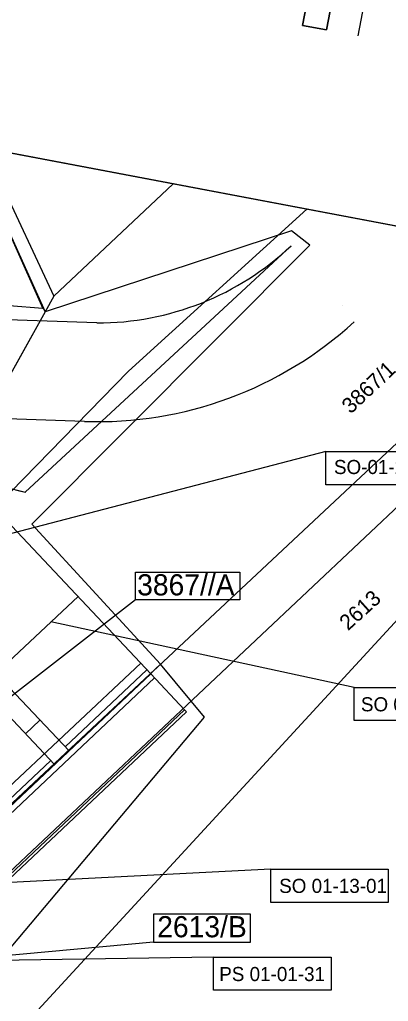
# Model space of a CAD drawing. Extents: x -526979 to -525529, y -1078878 to -1076692.
# Drawn here: x -526680.9 to -526628.5, y -1078144.8 to -1078005.6 of the extents above; entities that cross this region are included whole.
import ezdxf

# ---------------------------------------------------------------- set-up
doc = ezdxf.new("R2010")
doc.units = 0
for name, color, linetype in [('DZ_DO_ostatní', 7, 'Continuous'), ('Hranice parcel', 7, 'Continuous'), ('legenda barvy', 7, 'Continuous'), ('Parcelní čísla', 7, 'Continuous'), ('SO 01-50-01 silnice', 7, 'Continuous'), ('SO 01-50-01 silnice odvodnění', 7, 'Continuous'), ('Vnitřní kresba', 7, 'Continuous'), ('Vrstva 10', 7, 'Continuous'), ('Vrstva 12', 7, 'Continuous'), ('Vrstva 21', 7, 'Continuous'), ('Vrstva 63', 7, 'Continuous')]:
    doc.layers.add(name, color=color, linetype=linetype)

msp = doc.modelspace()

# ---------------------------------------------------------------- linework, layer by layer
at = {"layer": 'DZ_DO_ostatní'}
for points in [[(-526703.48, -1078093.97), (-526704.77, -1078090.39), (-526703.79, -1078090.05), (-526704.64, -1078087.24), (-526706.6, -1078087.88), (-526707.36, -1078085.92), (-526725.33, -1078039.65), (-526687.74, -1078023.95), (-526677.32, -1078047.05)], [(-526660.92, -1078096.98), (-526679.17, -1078077.14), (-526639.73, -1078037.59), (-526642.32, -1078035.55), (-526677.32, -1078047.05), (-526703.48, -1078093.97), (-526693.98, -1078127.86)], [(-526691.28, -1078138.22), (-526690.31, -1078138), (-526688.44, -1078144.53), (-526654.67, -1078104.54), (-526660.92, -1078096.98), (-526693.98, -1078127.86)]]:
    msp.add_lwpolyline(points, close=True, dxfattribs=at)
at = {"layer": 'Hranice parcel'}
for p, q in [((-526677.32, -1078047.05), (-526687.97, -1078023.43)), ((-526685.9, -1078023.82), (-526676.08, -1078044.81)), ((-526659.14, -1078028.88), (-526676.08, -1078044.81)), ((-526676.08, -1078044.81), (-526677.32, -1078047.05)), ((-526677.32, -1078047.05), (-526703.92, -1078094.77))]:
    msp.add_line(p, q, dxfattribs=at)
for points in [[(-526599.99, -1078040.07), (-526701.2, -1078134.61)], [(-526678.88, -1078146.61), (-526612.88, -1078075.09), (-526577.21, -1078044.38)]]:
    msp.add_lwpolyline(points, dxfattribs=at)
at = {"layer": 'legenda barvy'}
msp.add_line((-526631.15, -1077998.78), (-526632.87, -1078007.9), dxfattribs=at)
msp.add_lwpolyline([(-526640.73, -1078006.42), (-526639.01, -1077997.3), (-526635.6, -1077997.95), (-526637.32, -1078007.06)], close=True, dxfattribs=at)
msp.add_lwpolyline([(-526637.32, -1078007.06), (-526635.6, -1077997.95), (-526639.01, -1077997.3), (-526640.73, -1078006.42), (-526637.32, -1078007.06)], dxfattribs=at)
at = {"layer": 'SO 01-50-01 silnice'}
for p, q in [((-526683.54, -1078075.83), (-526662.3, -1078098.38)), ((-526738.98, -1078149.54), (-526672.62, -1078087.42)), ((-526730.03, -1078158.96), (-526663.71, -1078096.88)), ((-526674.46, -1078108.73), (-526662.85, -1078097.8)), ((-526705.48, -1078139.04), (-526662.3, -1078098.38)), ((-526705.27, -1078139.94), (-526661.75, -1078098.96)), ((-526662.3, -1078098.38), (-526657.5, -1078103.48)), ((-526703.63, -1078146.91), (-526657.5, -1078103.48)), ((-526703.52, -1078147.36), (-526657.23, -1078103.77)), ((-526657.5, -1078103.48), (-526657.23, -1078103.77)), ((-526705.69, -1078138.14), (-526676.5, -1078110.65))]:
    msp.add_line(p, q, dxfattribs=at)
at = {"layer": 'SO 01-50-01 silnice odvodnění'}
for p, q in [((-526698.68, -1078083.18), (-526673.91, -1078109.31)), ((-526700.71, -1078085.1), (-526675.95, -1078111.23)), ((-526680.07, -1078106.87), (-526678.04, -1078104.95)), ((-526675.95, -1078111.23), (-526673.91, -1078109.3))]:
    msp.add_line(p, q, dxfattribs=at)
at = {"layer": 'Vnitřní kresba'}
for p, q in [((-526665.48, -1078055.45), (-526640.13, -1078032.48)), ((-526592.05, -1078041.57), (-526699.08, -1078142.21)), ((-526703.92, -1078094.77), (-526665.48, -1078055.45))]:
    msp.add_line(p, q, dxfattribs=at)
at = {"layer": 'Vrstva 10'}
for p, q in [((-526680.13, -1078072.63), (-526642.36, -1078037.66)), ((-526680.13, -1078072.63), (-526642.36, -1078037.66)), ((-526669.96, -1078048.61), (-526740.65, -1078046.22)), ((-526669.96, -1078048.61), (-526740.65, -1078046.22)), ((-526635.13, -1078046.12), (-526635.11, -1078046.13)), ((-526635.13, -1078046.12), (-526635.11, -1078046.13)), ((-526671.72, -1078062.58), (-526741.08, -1078060.21)), ((-526671.72, -1078062.58), (-526741.08, -1078060.21))]:
    msp.add_line(p, q, dxfattribs=at)
for points in [[(-526690.93, -1078028.82), (-526686.47, -1078026.8), (-526677.65, -1078046.58), (-526682.41, -1078046.21), (-526690.93, -1078028.82)], [(-526690.93, -1078028.82), (-526686.47, -1078026.8), (-526677.65, -1078046.58), (-526682.41, -1078046.21), (-526690.93, -1078028.82)], [(-526681.52, -1078072.29), (-526680.92, -1078072.44), (-526680.13, -1078072.63)], [(-526681.52, -1078072.29), (-526680.92, -1078072.44), (-526680.13, -1078072.63)]]:
    msp.add_lwpolyline(points, dxfattribs=at)
for centre, radius, start, end in [((-526669.87, -1078008.57), 40.04, 269.8845, 313.4032), ((-526669.87, -1078008.57), 40.04, 269.8845, 313.4032), ((-526669.88, -1078008.55), 54.06, 268.0422, 312.3982), ((-526669.88, -1078008.55), 54.06, 268.0422, 312.3982), ((-526709.02, -1078189.1), 120, 76.0442, 108.9685), ((-526709.02, -1078189.1), 120, 76.0442, 108.9685)]:
    msp.add_arc(centre, radius, start, end, dxfattribs=at)
at = {"layer": 'Vrstva 12'}
for p, q in [((-526637.42, -1078066.85), (-526707.9, -1078085.2)), ((-526633.4, -1078100.29), (-526676.49, -1078091.02)), ((-526645.24, -1078126.09), (-526709.82, -1078129.34)), ((-526653.38, -1078138.55), (-526690.05, -1078139.1))]:
    msp.add_line(p, q, dxfattribs=at)
for points in [[(-526637.42, -1078066.85), (-526620.73, -1078066.85), (-526620.73, -1078071.55), (-526637.42, -1078071.55)], [(-526633.4, -1078100.29), (-526616.71, -1078100.29), (-526616.71, -1078104.99), (-526633.4, -1078104.99)], [(-526645.24, -1078126.09), (-526628.56, -1078126.09), (-526628.56, -1078130.79), (-526645.24, -1078130.79)], [(-526653.38, -1078138.55), (-526636.7, -1078138.55), (-526636.7, -1078143.25), (-526653.38, -1078143.25)]]:
    msp.add_lwpolyline(points, close=True, dxfattribs=at)
at = {"layer": 'Vrstva 21'}
for p, q in [((-526664.49, -1078087.89), (-526699.7, -1078115.18)), ((-526661.93, -1078136.44), (-526693.69, -1078139.32))]:
    msp.add_line(p, q, dxfattribs=at)
for points in [[(-526664.49, -1078083.95), (-526649.64, -1078083.95), (-526649.64, -1078087.89), (-526664.49, -1078087.89)], [(-526661.93, -1078136.44), (-526648.14, -1078136.44), (-526648.14, -1078132.45), (-526661.93, -1078132.45)]]:
    msp.add_lwpolyline(points, close=True, dxfattribs=at)
at = {"layer": 'Vrstva 63'}
msp.add_line((-526531.27, -1078053.07), (-526823.09, -1077997.87), dxfattribs=at)
msp.add_lwpolyline([(-526823.09, -1077997.87), (-526784.07, -1077791.53), (-526492.24, -1077846.73), (-526531.27, -1078053.07)], close=True, dxfattribs=at)

# ---------------------------------------------------------------- texts
at = {"layer": 'Parcelní čísla'}
for s, rotation, p in [('3867/1', 43.1092, (-526633.91, -1078061.61)), ('2613', 42, (-526634.28, -1078092.33))]:
    msp.add_text(s, height=2.2, rotation=rotation, dxfattribs=at).set_placement(p)
at = {"layer": 'Vrstva 12'}
for s, p in [('SO-01-21-01', (-526636.28, -1078070.04)), ('SO 01-50-01', (-526632.45, -1078103.69)), ('SO 01-13-01', (-526644.06, -1078129.44)), ('PS 01-01-31', (-526652.57, -1078141.94))]:
    msp.add_text(s, height=2, dxfattribs=at).set_placement(p)
at = {"layer": 'Vrstva 21'}
for s, p in [('3867//A', (-526664.23, -1078087.25)), ('2613/B', (-526661.38, -1078135.73))]:
    msp.add_text(s, height=3, dxfattribs=at).set_placement(p)

doc.saveas('drawing.dxf')
